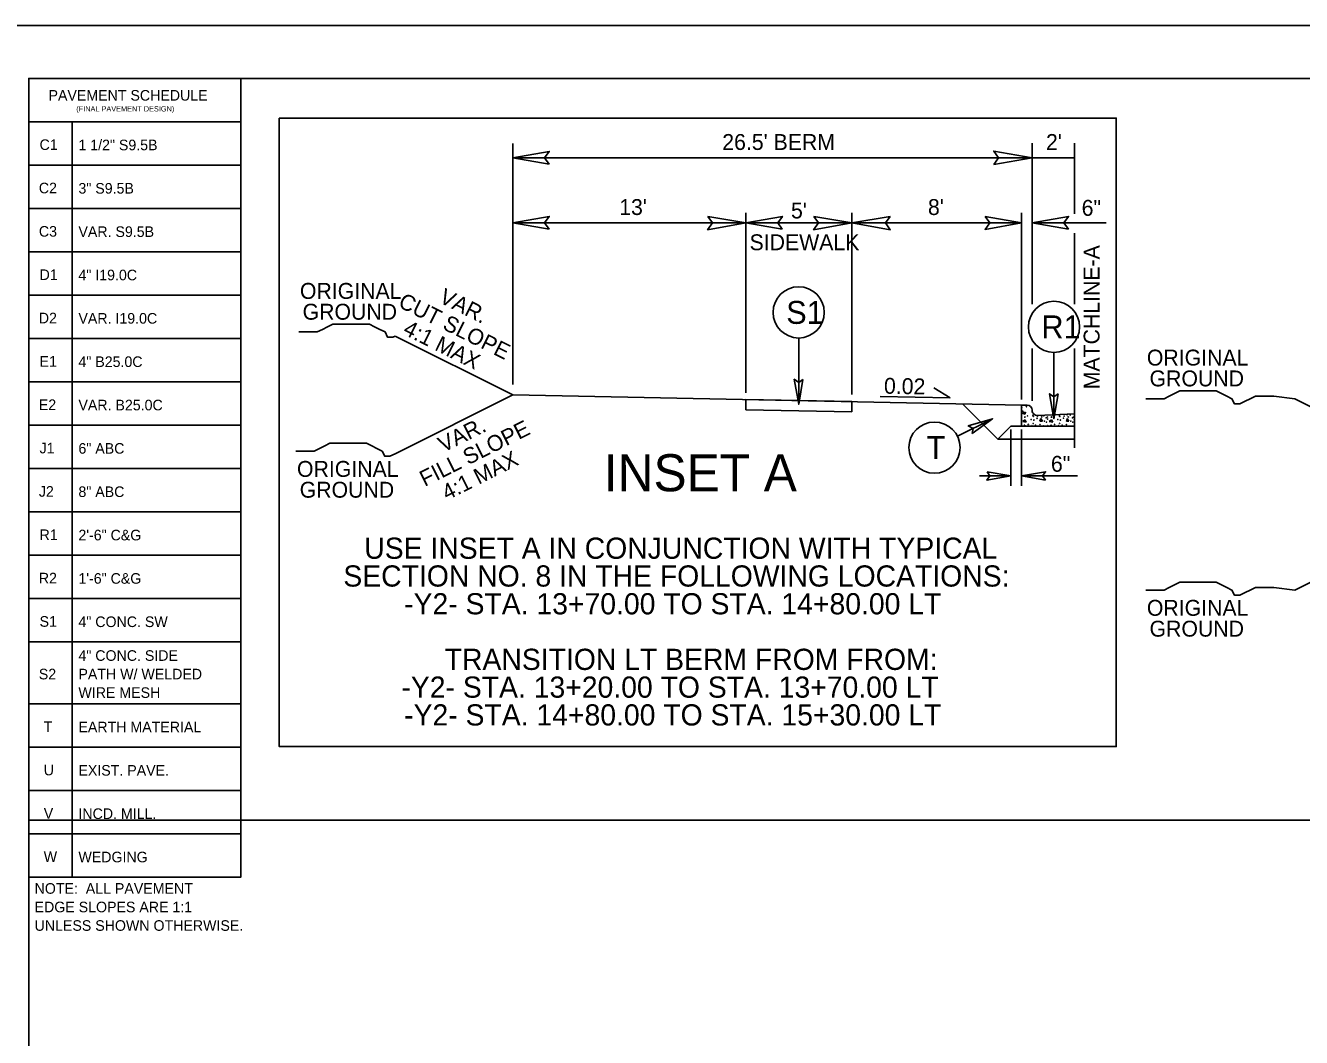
# Model space of a CAD drawing. Extents: x 1487909 to 1489267, y 497866 to 499814.
# Drawn here: x 1488899.8 to 1488960, y 498048.9 to 498096.7 of the extents above; entities that cross this region are included whole.
import ezdxf

# ---------------------------------------------------------------- set-up
doc = ezdxf.new("R2010")
doc.units = 0
for name, color, linetype in [('Prop Conc 4in Sidewalk', 7, 'Continuous'), ('Prop Dimension', 7, 'Continuous'), ('Prop Dimension Text', 7, 'Continuous'), ('Prop Pavement Schedule Description CELL', 7, 'Continuous'), ('Prop Shade Light', 7, 'Continuous'), ('Prop Terminator CELL', 7, 'Continuous'), ('Scratch_Level_1', 7, 'Continuous'), ('Sheet Plot Border Outside CELL', 7, 'Continuous'), ('Sheet Typical CELL', 7, 'Continuous'), ('Typical Curb CELL', 7, 'Continuous'), ('Typical Hinge Slope Arterial CELL', 7, 'Continuous'), ('Typical ID Circle CELL', 7, 'Continuous'), ('Typical Pavement Slope CELL', 7, 'Continuous'), ('Typical Pavement Slope Information CELL', 7, 'Continuous'), ('Typical Terminator CELL', 7, 'Continuous'), ('Typical Text ID Circle CELL', 7, 'Continuous')]:
    doc.layers.add(name, color=color, linetype=linetype)

msp = doc.modelspace()

# ---------------------------------------------------------------- linework, layer by layer
at = {"layer": 'Prop Conc 4in Sidewalk'}
for p, q in [((1488938.802, 498078.904), (1488933.802, 498079.004)), ((1488933.802, 498079.004), (1488933.802, 498078.523)), ((1488938.802, 498078.423), (1488933.802, 498078.523)), ((1488938.802, 498078.904), (1488938.802, 498078.423))]:
    msp.add_line(p, q, dxfattribs=at)
at = {"layer": 'Prop Dimension'}
for p, q in [((1488922.802, 498079.72), (1488922.802, 498091.089)), ((1488947.302, 498083.498), (1488947.302, 498091.11)), ((1488949.302, 498087.761), (1488949.302, 498091.11)), ((1488947.302, 498090.409), (1488922.802, 498090.409)), ((1488947.302, 498090.409), (1488949.302, 498090.409)), ((1488933.802, 498079.325), (1488933.802, 498087.811)), ((1488938.802, 498079.248), (1488938.802, 498087.811)), ((1488946.802, 498079.008), (1488946.802, 498087.811)), ((1488922.802, 498087.339), (1488933.802, 498087.339)), ((1488933.802, 498087.339), (1488938.802, 498087.339)), ((1488938.802, 498087.339), (1488946.802, 498087.339)), ((1488950.797, 498087.339), (1488947.302, 498087.339)), ((1488949.302, 498083.498), (1488949.302, 498086.858)), ((1488947.302, 498078.948), (1488947.302, 498081.418)), ((1488949.302, 498076.72), (1488949.302, 498081.418)), ((1488946.302, 498074.938), (1488946.302, 498077.592)), ((1488946.802, 498074.938), (1488946.802, 498077.592)), ((1488944.816, 498075.398), (1488946.302, 498075.398)), ((1488946.802, 498075.398), (1488949.45, 498075.398))]:
    msp.add_line(p, q, dxfattribs=at)
at = {"layer": 'Prop Pavement Schedule Description CELL'}
for points in [[(1488902.009, 498092.109), (1488899.964, 498092.109), (1488899.964, 498094.154), (1488909.964, 498094.154), (1488909.964, 498092.109), (1488902.009, 498092.109)], [(1488902.009, 498090.063), (1488899.964, 498090.063), (1488899.964, 498092.109), (1488909.964, 498092.109), (1488909.964, 498090.063), (1488902.009, 498090.063), (1488902.009, 498092.109)], [(1488902.009, 498088.018), (1488899.964, 498088.018), (1488899.964, 498090.063), (1488909.964, 498090.063), (1488909.964, 498088.018), (1488902.009, 498088.018), (1488902.009, 498090.063)], [(1488902.009, 498085.973), (1488899.964, 498085.973), (1488899.964, 498088.018), (1488909.964, 498088.018), (1488909.964, 498085.973), (1488902.009, 498085.973), (1488902.009, 498088.018)], [(1488902.009, 498083.927), (1488899.964, 498083.927), (1488899.964, 498085.973), (1488909.964, 498085.973), (1488909.964, 498083.927), (1488902.009, 498083.927), (1488902.009, 498085.973)], [(1488902.009, 498081.882), (1488899.964, 498081.882), (1488899.964, 498083.927), (1488909.964, 498083.927), (1488909.964, 498081.882), (1488902.009, 498081.882), (1488902.009, 498083.927)], [(1488902.009, 498079.836), (1488899.964, 498079.836), (1488899.964, 498081.882), (1488909.964, 498081.882), (1488909.964, 498079.836), (1488902.009, 498079.836), (1488902.009, 498081.882)], [(1488902.009, 498077.791), (1488899.964, 498077.791), (1488899.964, 498079.836), (1488909.964, 498079.836), (1488909.964, 498077.791), (1488902.009, 498077.791), (1488902.009, 498079.836)], [(1488902.009, 498075.745), (1488899.964, 498075.745), (1488899.964, 498077.791), (1488909.964, 498077.791), (1488909.964, 498075.745), (1488902.009, 498075.745), (1488902.009, 498077.791)], [(1488902.009, 498073.7), (1488899.964, 498073.7), (1488899.964, 498075.745), (1488909.964, 498075.745), (1488909.964, 498073.7), (1488902.009, 498073.7), (1488902.009, 498075.745)], [(1488902.009, 498071.655), (1488899.964, 498071.655), (1488899.964, 498073.7), (1488909.964, 498073.7), (1488909.964, 498071.655), (1488902.009, 498071.655), (1488902.009, 498073.7)], [(1488902.009, 498069.609), (1488899.964, 498069.609), (1488899.964, 498071.655), (1488909.964, 498071.655), (1488909.964, 498069.609), (1488902.009, 498069.609), (1488902.009, 498071.655)], [(1488902.009, 498067.564), (1488899.964, 498067.564), (1488899.964, 498069.609), (1488909.964, 498069.609), (1488909.964, 498067.564), (1488902.009, 498067.564), (1488902.009, 498069.609)], [(1488902.009, 498064.644), (1488899.964, 498064.644), (1488899.964, 498067.564), (1488909.964, 498067.564), (1488909.964, 498064.644), (1488902.009, 498064.644), (1488902.009, 498067.564)], [(1488902.009, 498062.598), (1488899.964, 498062.598), (1488899.964, 498064.644), (1488909.964, 498064.644), (1488909.964, 498062.598), (1488902.009, 498062.598), (1488902.009, 498064.644)], [(1488902.009, 498060.553), (1488899.964, 498060.553), (1488899.964, 498062.598), (1488909.964, 498062.598), (1488909.964, 498060.553), (1488902.009, 498060.553), (1488902.009, 498062.598)], [(1488902.009, 498058.507), (1488899.964, 498058.507), (1488899.964, 498060.553), (1488909.964, 498060.553), (1488909.964, 498058.507), (1488902.009, 498058.507), (1488902.009, 498060.553)], [(1488902.009, 498056.462), (1488899.964, 498056.462), (1488899.964, 498058.507), (1488909.964, 498058.507), (1488909.964, 498056.462), (1488902.009, 498056.462), (1488902.009, 498058.507)]]:
    msp.add_lwpolyline(points, dxfattribs=at)
at = {"layer": 'Prop Shade Light'}
for p, q in [((1488938.802, 498078.904), (1488933.802, 498079.004)), ((1488933.802, 498079.004), (1488933.802, 498078.523)), ((1488933.802, 498078.523), (1488938.802, 498078.423)), ((1488938.802, 498078.423), (1488938.802, 498078.904))]:
    msp.add_line(p, q, dxfattribs=at)
at = {"layer": 'Prop Terminator CELL'}
for points in [[(1488924.512, 498090.114), (1488922.802, 498090.409), (1488924.521, 498090.713), (1488924.303, 498090.409)], [(1488945.502, 498090.099), (1488947.302, 498090.409), (1488945.492, 498090.729), (1488945.722, 498090.409)], [(1488924.512, 498087.045), (1488922.802, 498087.339), (1488924.521, 498087.643), (1488924.303, 498087.339)], [(1488932.002, 498087.649), (1488933.802, 498087.339), (1488931.992, 498087.019), (1488932.222, 498087.339)], [(1488935.512, 498087.045), (1488933.802, 498087.339), (1488935.521, 498087.643), (1488935.303, 498087.339)], [(1488937.002, 498087.649), (1488938.802, 498087.339), (1488936.992, 498087.019), (1488937.222, 498087.339)], [(1488940.602, 498087.649), (1488938.802, 498087.339), (1488940.612, 498087.019), (1488940.382, 498087.339)], [(1488945.092, 498087.634), (1488946.802, 498087.339), (1488945.082, 498087.035), (1488945.301, 498087.339)], [(1488949.012, 498087.045), (1488947.302, 498087.339), (1488949.021, 498087.643), (1488948.803, 498087.339)], [(1488945.177, 498075.591), (1488946.302, 498075.398), (1488945.171, 498075.198), (1488945.315, 498075.398)], [(1488947.927, 498075.204), (1488946.802, 498075.398), (1488947.934, 498075.598), (1488947.79, 498075.398)]]:
    msp.add_lwpolyline(points, close=True, dxfattribs=at)
at = {"layer": 'Scratch_Level_1'}
msp.add_line((1488899.964, 498059.154), (1489049.964, 498059.154), dxfattribs=at)
at = {"layer": 'Sheet Plot Border Outside CELL'}
msp.add_lwpolyline([(1489051.664, 498096.654), (1488883.264, 498096.654), (1488883.264, 497986.654), (1489051.664, 497986.654)], close=True, dxfattribs=at)
at = {"layer": 'Sheet Typical CELL'}
for points in [[(1489049.964, 498094.154), (1488899.964, 498094.154), (1488899.964, 497989.154), (1489049.964, 497989.154)], [(1488911.778, 498092.287), (1488951.273, 498092.287), (1488951.273, 498062.624), (1488911.778, 498062.624)]]:
    msp.add_lwpolyline(points, close=True, dxfattribs=at)
at = {"layer": 'Typical Curb CELL'}
for p, q in [((1488946.802, 498077.744), (1488946.802, 498078.744)), ((1488946.802, 498078.744), (1488947.063, 498078.744)), ((1488946.839, 498078.366), (1488946.993, 498078.411)), ((1488946.976, 498078.32), (1488946.839, 498078.366)), ((1488946.993, 498078.411), (1488946.976, 498078.32)), ((1488947.302, 498078.494), (1488947.302, 498078.505)), ((1488946.965, 498078.047), (1488946.862, 498077.972)), ((1488946.862, 498077.972), (1488947.027, 498077.933)), ((1488947.027, 498077.933), (1488946.965, 498078.047)), ((1488949.302, 498078.327), (1488947.552, 498078.255)), ((1488947.706, 498078.104), (1488947.672, 498077.99)), ((1488947.672, 498077.99), (1488947.792, 498077.984)), ((1488947.792, 498077.984), (1488947.706, 498078.104)), ((1488948.214, 498078.047), (1488948.111, 498077.972)), ((1488948.111, 498077.972), (1488948.276, 498077.933)), ((1488948.276, 498077.933), (1488948.214, 498078.047)), ((1488948.955, 498078.104), (1488948.921, 498077.99)), ((1488948.921, 498077.99), (1488949.042, 498077.984)), ((1488949.042, 498077.984), (1488948.955, 498078.104)), ((1488949.302, 498077.744), (1488949.302, 498078.327)), ((1488946.802, 498077.744), (1488949.302, 498077.744))]:
    msp.add_line(p, q, dxfattribs=at)
for centre in [(1488946.816, 498078.634), (1488946.867, 498078.451), (1488947.033, 498078.668), (1488946.947, 498077.79), (1488946.964, 498078.178), (1488947.084, 498078.229), (1488947.118, 498077.83), (1488947.261, 498078.064), (1488947.295, 498077.767), (1488947.341, 498078.257), (1488947.353, 498077.881), (1488947.358, 498078.207), (1488947.387, 498078.036), (1488947.467, 498077.796), (1488947.535, 498078.121), (1488947.564, 498078.223), (1488947.672, 498077.819), (1488947.758, 498078.184), (1488947.832, 498077.75), (1488947.855, 498078.238), (1488947.883, 498077.984), (1488947.963, 498078.144), (1488947.979, 498077.938), (1488948.019, 498078.178), (1488948.036, 498078.081), (1488948.042, 498077.773), (1488948.196, 498077.79), (1488948.213, 498078.178), (1488948.333, 498078.229), (1488948.367, 498077.83), (1488948.51, 498078.064), (1488948.544, 498077.767), (1488948.59, 498078.257), (1488948.602, 498077.881), (1488948.607, 498078.207), (1488948.636, 498078.036), (1488948.716, 498077.796), (1488948.784, 498078.121), (1488948.813, 498078.223), (1488948.921, 498077.819), (1488948.961, 498078.286), (1488949.007, 498078.184), (1488949.081, 498077.75), (1488949.104, 498078.269), (1488949.132, 498077.984), (1488949.212, 498078.144), (1488949.228, 498077.938), (1488949.268, 498078.178), (1488949.285, 498078.081), (1488949.291, 498077.773)]:
    msp.add_circle(centre, 0.00802, dxfattribs=at)
for centre, start, end in [((1488947.063, 498078.505), 0, 90), ((1488947.542, 498078.494), 180, 272.38446)]:
    msp.add_arc(centre, 0.24, start, end, dxfattribs=at)
at = {"layer": 'Typical Hinge Slope Arterial CELL'}
for p, q in [((1488917.251, 498081.999), (1488922.802, 498079.224)), ((1488922.802, 498079.224), (1488917.251, 498076.449)), ((1488959.69, 498079.045), (1488968.719, 498074.531)), ((1488968.719, 498074.531), (1488959.69, 498070.016))]:
    msp.add_line(p, q, dxfattribs=at)
for points in [[(1488917.251, 498081.999), (1488917.142, 498081.944), (1488916.896, 498081.944), (1488916.772, 498082.192), (1488916.526, 498082.314), (1488916.279, 498082.438), (1488916.033, 498082.561), (1488915.787, 498082.561), (1488915.54, 498082.561), (1488915.294, 498082.561), (1488915.048, 498082.561), (1488914.801, 498082.561), (1488914.555, 498082.561), (1488914.308, 498082.561), (1488914.062, 498082.438), (1488913.816, 498082.314), (1488913.569, 498082.192), (1488913.199, 498082.192), (1488912.953, 498082.192), (1488912.707, 498082.192)], [(1488959.69, 498079.045), (1488958.704, 498079.168), (1488958.458, 498079.168), (1488958.088, 498079.168), (1488957.841, 498079.168), (1488957.595, 498079.045), (1488957.349, 498078.922), (1488957.102, 498078.798), (1488956.856, 498078.798), (1488956.732, 498079.045), (1488956.486, 498079.168), (1488956.24, 498079.292), (1488955.993, 498079.414), (1488955.747, 498079.414), (1488955.5, 498079.414), (1488955.254, 498079.414), (1488955.008, 498079.414), (1488954.761, 498079.414), (1488954.515, 498079.414), (1488954.269, 498079.414), (1488954.022, 498079.292), (1488953.776, 498079.168), (1488953.53, 498079.045), (1488953.159, 498079.045), (1488952.913, 498079.045), (1488952.667, 498079.045)], [(1488917.251, 498076.449), (1488917.005, 498076.325), (1488916.759, 498076.325), (1488916.635, 498076.573), (1488916.389, 498076.695), (1488916.142, 498076.819), (1488915.896, 498076.942), (1488915.65, 498076.942), (1488915.403, 498076.942), (1488915.157, 498076.942), (1488914.91, 498076.942), (1488914.664, 498076.942), (1488914.418, 498076.942), (1488914.171, 498076.942), (1488913.925, 498076.819), (1488913.679, 498076.695), (1488913.432, 498076.573), (1488913.062, 498076.573), (1488912.816, 498076.573), (1488912.569, 498076.573)], [(1488959.69, 498070.016), (1488958.704, 498070.139), (1488958.458, 498070.139), (1488958.088, 498070.139), (1488957.841, 498070.139), (1488957.595, 498070.016), (1488957.349, 498069.893), (1488957.102, 498069.769), (1488956.856, 498069.769), (1488956.732, 498070.016), (1488956.486, 498070.139), (1488956.24, 498070.263), (1488955.993, 498070.385), (1488955.747, 498070.385), (1488955.5, 498070.385), (1488955.254, 498070.385), (1488955.008, 498070.385), (1488954.761, 498070.385), (1488954.515, 498070.385), (1488954.269, 498070.385), (1488954.022, 498070.263), (1488953.776, 498070.139), (1488953.53, 498070.016), (1488953.159, 498070.016), (1488952.913, 498070.016), (1488952.667, 498070.016)]]:
    msp.add_lwpolyline(points, dxfattribs=at)
at = {"layer": 'Typical ID Circle CELL'}
for p, q in [((1488936.288, 498081.908), (1488936.288, 498078.784)), ((1488948.334, 498081.224), (1488948.334, 498078.101)), ((1488943.777, 498077.274), (1488945.435, 498078.098))]:
    msp.add_line(p, q, dxfattribs=at)
for centre in [(1488936.288, 498083.116), (1488948.334, 498082.433), (1488942.695, 498076.736)]:
    msp.add_circle(centre, 1.208, dxfattribs=at)
at = {"layer": 'Typical Pavement Slope CELL'}
for p, q in [((1488946.802, 498078.744), (1488922.802, 498079.224)), ((1488944.021, 498078.8), (1488945.689, 498077.131)), ((1488946.302, 498077.744), (1488945.689, 498077.131)), ((1488946.802, 498077.744), (1488946.302, 498077.744)), ((1488949.302, 498077.131), (1488945.689, 498077.131))]:
    msp.add_line(p, q, dxfattribs=at)
at = {"layer": 'Typical Pavement Slope Information CELL'}
for q in [(1488940.127, 498079.146), (1488942.66, 498079.553)]:
    msp.add_line((1488943.443, 498079.08), q, dxfattribs=at)
at = {"layer": 'Typical Terminator CELL'}
for points in [[(1488936.489, 498079.956), (1488936.288, 498078.784), (1488936.079, 498079.963), (1488936.288, 498079.813)], [(1488936.489, 498079.956), (1488936.288, 498078.784), (1488936.079, 498079.963), (1488936.288, 498079.813)], [(1488948.536, 498079.273), (1488948.334, 498078.101), (1488948.126, 498079.279), (1488948.334, 498079.13)], [(1488944.475, 498077.396), (1488945.435, 498078.098), (1488944.287, 498077.76), (1488944.514, 498077.64)]]:
    msp.add_lwpolyline(points, close=True, dxfattribs=at)

# ---------------------------------------------------------------- texts
at = {"layer": 'Prop Dimension Text'}
for s, p in [("26.5' BERM", (1488932.683, 498090.782)), ("2'", (1488947.957, 498090.782)), ("13'", (1488927.821, 498087.713)), ("5'", (1488935.926, 498087.55)), ("8'", (1488942.387, 498087.713)), ('6"', (1488949.64, 498087.675)), ('SIDEWALK', (1488933.971, 498086.05)), ('6"', (1488948.19, 498075.596))]:
    msp.add_text(s, height=0.75, dxfattribs=at).set_placement(p)
at = {"layer": 'Prop Pavement Schedule Description CELL'}
for s, height, p in [('PAVEMENT SCHEDULE', 0.5, (1488900.896, 498093.11)), ('(FINAL PAVEMENT DESIGN)', 0.25, (1488902.206, 498092.598)), ('C1', 0.5, (1488900.473, 498090.782)), (' 1 1/2" S9.5B', 0.5, (1488902.121, 498090.767)), ('C2', 0.5, (1488900.438, 498088.736)), (' 3" S9.5B', 0.5, (1488902.121, 498088.722)), ('C3', 0.5, (1488900.441, 498086.691)), (' VAR. S9.5B', 0.5, (1488902.121, 498086.676)), ('D1', 0.5, (1488900.473, 498084.645)), (' 4" I19.0C', 0.5, (1488902.121, 498084.631)), ('D2', 0.5, (1488900.438, 498082.6)), (' VAR. I19.0C', 0.5, (1488902.121, 498082.586)), ('E1', 0.5, (1488900.473, 498080.555)), (' 4" B25.0C', 0.5, (1488902.121, 498080.54)), ('E2', 0.5, (1488900.438, 498078.509)), (' VAR. B25.0C', 0.5, (1488902.121, 498078.495)), ('J1', 0.5, (1488900.473, 498076.464)), (' 6" ABC', 0.5, (1488902.121, 498076.449)), ('J2', 0.5, (1488900.438, 498074.418)), (' 8" ABC', 0.5, (1488902.121, 498074.404)), ('R1', 0.5, (1488900.473, 498072.373)), (' 2\'-6" C&G', 0.5, (1488902.121, 498072.359)), ('R2', 0.5, (1488900.438, 498070.328)), (' 1\'-6" C&G', 0.5, (1488902.121, 498070.313)), ('S1', 0.5, (1488900.473, 498068.282)), (' 4" CONC. SW', 0.5, (1488902.121, 498068.268)), (' 4" CONC. SIDE', 0.5, (1488902.121, 498066.674)), (' PATH W/ WELDED', 0.5, (1488902.121, 498065.799)), ('S2', 0.5, (1488900.438, 498065.799)), (' WIRE MESH', 0.5, (1488902.121, 498064.925)), ('T', 0.5, (1488900.669, 498063.317)), (' EARTH MATERIAL', 0.5, (1488902.121, 498063.302)), ('U', 0.5, (1488900.669, 498061.271)), (' EXIST. PAVE.', 0.5, (1488902.121, 498061.257)), ('V', 0.5, (1488900.671, 498059.226)), (' INCD. MILL.', 0.5, (1488902.121, 498059.211)), ('W', 0.5, (1488900.669, 498057.18)), (' WEDGING', 0.5, (1488902.121, 498057.166)), ('NOTE:  ALL PAVEMENT', 0.5, (1488900.238, 498055.683)), ('EDGE SLOPES ARE 1:1 ', 0.5, (1488900.238, 498054.808)), ('UNLESS SHOWN OTHERWISE.', 0.5, (1488900.238, 498053.934))]:
    msp.add_text(s, height=height, dxfattribs=at).set_placement(p)
at = {"layer": 'Typical Hinge Slope Arterial CELL'}
for s, rotation, p in [('MATCHLINE-A', 90, (1488950.483, 498079.489)), ('CUT SLOPE', 333.46576, (1488917.345, 498083.401)), ('VAR.', 333.46576, (1488919.272, 498083.613)), ('4:1 MAX', 333.46576, (1488917.573, 498082.114)), ('FILL SLOPE', 26.53424, (1488918.644, 498074.879)), ('VAR.', 26.53424, (1488919.518, 498076.489)), ('4:1 MAX', 26.53424, (1488919.695, 498074.231))]:
    msp.add_text(s, height=0.75, rotation=rotation, dxfattribs=at).set_placement(p)
for s, height, p in [('ORIGINAL', 0.75, (1488912.756, 498083.756)), ('GROUND', 0.75, (1488912.882, 498082.772)), ('ORIGINAL', 0.75, (1488952.716, 498080.609)), ('GROUND', 0.75, (1488952.842, 498079.626)), ('ORIGINAL', 0.75, (1488912.618, 498075.356)), ('GROUND', 0.75, (1488912.745, 498074.373)), ('USE INSET A IN CONJUNCTION WITH TYPICAL', 1, (1488915.791, 498071.489)), ('SECTION NO. 8 IN THE FOLLOWING LOCATIONS:', 1, (1488914.805, 498070.178)), ('-Y2- STA. 13+70.00 TO STA. 14+80.00 LT', 1, (1488917.674, 498068.867)), ('ORIGINAL', 0.75, (1488952.716, 498068.8)), ('GROUND', 0.75, (1488952.842, 498067.816)), ('TRANSITION LT BERM FROM FROM:', 1, (1488919.587, 498066.245)), (' -Y2- STA. 13+20.00 TO STA. 13+70.00 LT', 1, (1488917.174, 498064.934)), ('-Y2- STA. 14+80.00 TO STA. 15+30.00 LT', 1, (1488917.674, 498063.623))]:
    msp.add_text(s, height=height, dxfattribs=at).set_placement(p)
at = {"layer": 'Typical Pavement Slope CELL'}
msp.add_text('INSET A', height=1.75, dxfattribs=at).set_placement((1488927.099, 498074.675))
at = {"layer": 'Typical Pavement Slope Information CELL'}
msp.add_text('0.02', height=0.75, rotation=358.85426, dxfattribs=at).set_placement((1488940.307, 498079.282))
at = {"layer": 'Typical Text ID Circle CELL'}
for s, height, p in [('S1', 1.0817, (1488935.7, 498082.575)), ('R1', 1.0817, (1488947.741, 498081.892)), ('T', 1.082, (1488942.32, 498076.195))]:
    msp.add_text(s, height=height, dxfattribs=at).set_placement(p)

doc.saveas('drawing.dxf')
